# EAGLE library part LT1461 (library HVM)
VOLTAGE REFERENCE. SUFFIX SPECIFIES VOLTAGE OUT.
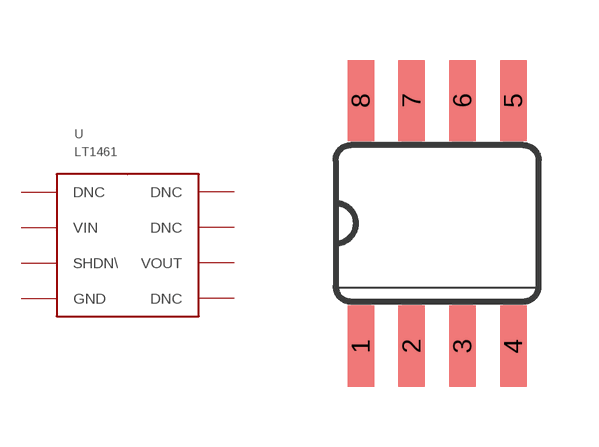
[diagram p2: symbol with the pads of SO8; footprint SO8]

Designator prefix U

## LT1461  [SO8]
1  DNC  nc
2  VIN  pas
3  SHDN\  pas
4  GND  pas
5  DNC  nc
6  VOUT  pas
7  DNC  nc
8  DNC  nc

## Footprint SO8 (pad centres in mm)
SO8 PACKAGE
smd 0.66 x 2.032: 1 -1.905,-3.073; 2 -0.635,-3.073; 3 0.635,-3.073; 4 1.905,-3.073; 5 1.905,3.073; 6 0.635,3.073; 7 -0.635,3.073; 8 -1.905,3.073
